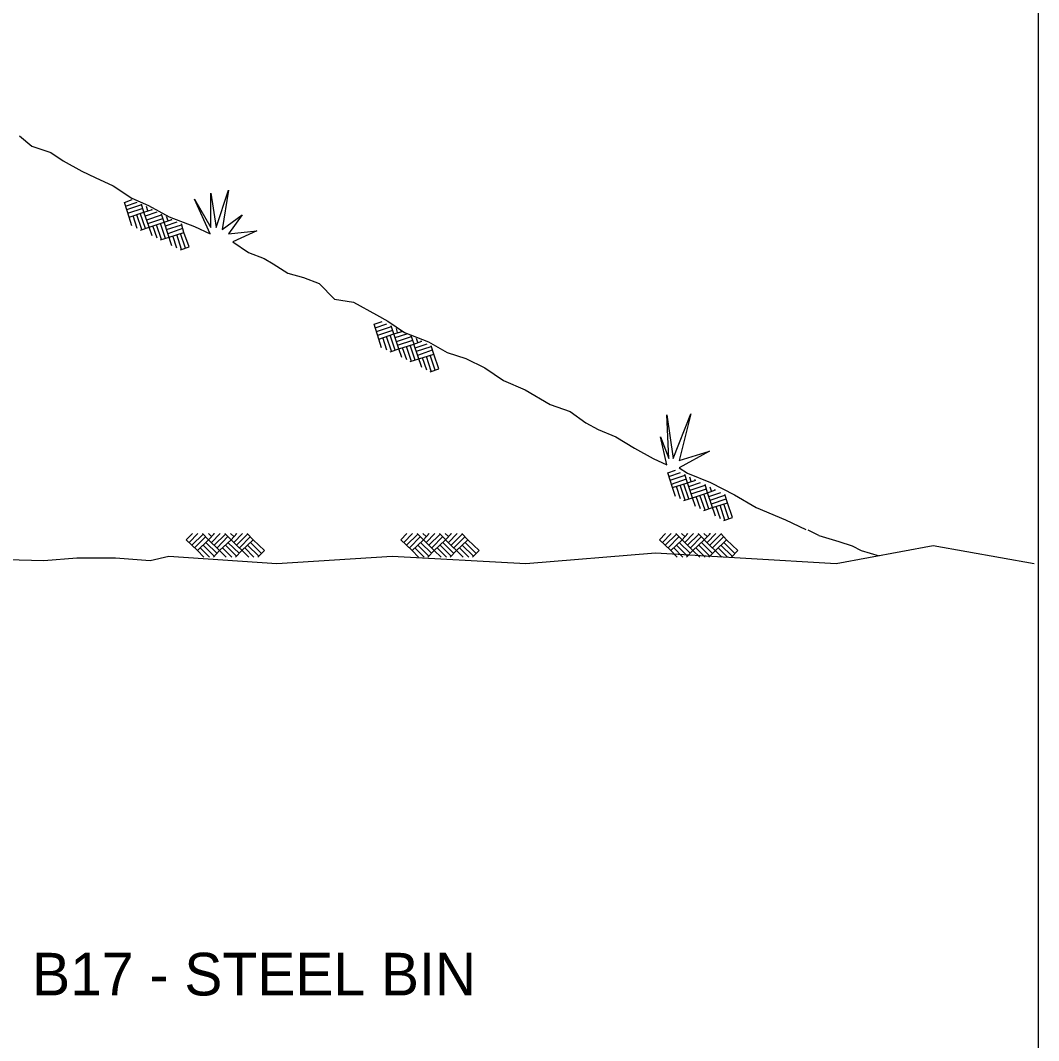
# Model space of a CAD drawing. Extents: x -0.04 to 2.79, y -0.02 to 1.81.
# Drawn here: x 2.2693 to 2.5178, y 0.5127 to 0.7618 of the extents above; entities that cross this region are included whole.
import ezdxf

# ---------------------------------------------------------------- set-up
doc = ezdxf.new("R2010")
doc.units = 0
doc.layers.add('G-ANNO-TTLB', color=7, linetype='Continuous')
doc.layers.add('Level 1', color=7, linetype='Continuous')

msp = doc.modelspace()

# ---------------------------------------------------------------- linework, layer by layer
at = {"layer": 'G-ANNO-TTLB'}
msp.add_line((2.51784, 0.08028), (2.51784, 1.71305), dxfattribs=at)
at = {"layer": 'Level 1'}
for p, q in [((2.29464, 0.71733), (2.29655, 0.71801)), ((2.2958, 0.71371), (2.29464, 0.71733)), ((2.29491, 0.71644), (2.29778, 0.7174)), ((2.29526, 0.71555), (2.29888, 0.71678)), ((2.29553, 0.71466), (2.29922, 0.71589)), ((2.2958, 0.71371), (2.29943, 0.71494)), ((2.29943, 0.71494), (2.29881, 0.71692)), ((2.29943, 0.71494), (2.30148, 0.71555)), ((2.29943, 0.71494), (2.30148, 0.71555)), ((2.30066, 0.71131), (2.29943, 0.71494)), ((2.29977, 0.71405), (2.30264, 0.715)), ((2.30038, 0.71528), (2.30004, 0.7163)), ((2.30134, 0.71555), (2.30127, 0.71569)), ((2.29649, 0.71159), (2.2958, 0.71371)), ((2.29778, 0.71097), (2.29676, 0.71405)), ((2.29888, 0.7107), (2.29765, 0.71432)), ((2.29977, 0.71097), (2.29854, 0.71466)), ((2.30011, 0.71309), (2.30373, 0.71432)), ((2.30038, 0.7122), (2.30407, 0.71343)), ((2.30066, 0.71131), (2.30435, 0.71248)), ((2.30435, 0.71248), (2.30373, 0.71446)), ((2.30435, 0.71248), (2.30633, 0.71316)), ((2.30435, 0.71248), (2.30633, 0.71316)), ((2.30626, 0.70673), (2.30435, 0.71248)), ((2.30469, 0.71159), (2.30756, 0.71254)), ((2.3053, 0.71282), (2.30496, 0.71384)), ((2.30619, 0.71309), (2.30612, 0.71323)), ((2.29861, 0.71056), (2.30066, 0.71131)), ((2.30141, 0.70919), (2.30066, 0.71131)), ((2.30264, 0.70858), (2.30161, 0.71159)), ((2.30373, 0.70824), (2.3025, 0.71186)), ((2.30469, 0.70851), (2.30346, 0.7122)), ((2.30496, 0.7107), (2.30858, 0.71186)), ((2.3053, 0.70974), (2.30893, 0.71104)), ((2.30558, 0.70885), (2.3092, 0.71001)), ((2.3092, 0.71001), (2.30858, 0.71207)), ((2.31043, 0.70646), (2.3092, 0.71001)), ((2.30346, 0.70817), (2.30558, 0.70885)), ((2.30749, 0.70612), (2.30647, 0.70913)), ((2.30858, 0.70585), (2.30742, 0.70947)), ((2.30954, 0.70612), (2.30831, 0.70974)), ((2.30831, 0.70571), (2.31043, 0.70646)), ((2.35561, 0.6876), (2.35759, 0.68828)), ((2.35677, 0.68397), (2.35561, 0.6876)), ((2.35588, 0.68671), (2.35875, 0.68766)), ((2.35622, 0.68582), (2.35985, 0.68705)), ((2.3565, 0.68493), (2.36019, 0.68616)), ((2.35677, 0.68397), (2.36046, 0.6852)), ((2.36074, 0.68124), (2.35951, 0.68493)), ((2.36046, 0.6852), (2.35978, 0.68719)), ((2.36046, 0.6852), (2.36244, 0.68582)), ((2.36046, 0.6852), (2.36244, 0.68582)), ((2.36169, 0.68158), (2.36046, 0.6852)), ((2.36074, 0.68431), (2.36361, 0.68527)), ((2.36135, 0.68555), (2.36108, 0.68657)), ((2.36231, 0.68582), (2.36224, 0.68596)), ((2.35746, 0.68185), (2.35677, 0.68397)), ((2.35875, 0.68124), (2.35773, 0.68431)), ((2.35985, 0.68097), (2.35862, 0.68459)), ((2.36108, 0.68336), (2.36477, 0.68459)), ((2.36135, 0.68247), (2.36504, 0.6837)), ((2.36169, 0.68158), (2.36532, 0.68274)), ((2.36566, 0.67878), (2.36443, 0.68247)), ((2.36538, 0.68274), (2.3647, 0.68472)), ((2.36532, 0.68274), (2.3673, 0.68343)), ((2.36532, 0.68274), (2.3673, 0.68343)), ((2.36723, 0.677), (2.36532, 0.68274)), ((2.36566, 0.68185), (2.36853, 0.68281)), ((2.36627, 0.68308), (2.36593, 0.68411)), ((2.36716, 0.68336), (2.36709, 0.68349)), ((2.35957, 0.68083), (2.36169, 0.68158)), ((2.36238, 0.67946), (2.36169, 0.68158)), ((2.36361, 0.67885), (2.36258, 0.68185)), ((2.36477, 0.6785), (2.36354, 0.68213)), ((2.36593, 0.68097), (2.36955, 0.68213)), ((2.36627, 0.68001), (2.3699, 0.68131)), ((2.36655, 0.67912), (2.37017, 0.68028)), ((2.37051, 0.67639), (2.36928, 0.68001)), ((2.37017, 0.68028), (2.36955, 0.68233)), ((2.3714, 0.67673), (2.37017, 0.68028)), ((2.36443, 0.67844), (2.36655, 0.67912)), ((2.36846, 0.67639), (2.36743, 0.67939)), ((2.36955, 0.67611), (2.36839, 0.67974)), ((2.36928, 0.67598), (2.3714, 0.67673)), ((2.42731, 0.6513), (2.42922, 0.65198)), ((2.42847, 0.64768), (2.42731, 0.6513)), ((2.42758, 0.65041), (2.43045, 0.65137)), ((2.42792, 0.64952), (2.43155, 0.65069)), ((2.43209, 0.64884), (2.43148, 0.65089)), ((2.43305, 0.64918), (2.43271, 0.65028)), ((2.4282, 0.64857), (2.43189, 0.6498)), ((2.42847, 0.64768), (2.43209, 0.64884)), ((2.42916, 0.64556), (2.42847, 0.64768)), ((2.43045, 0.64494), (2.42943, 0.64795)), ((2.43155, 0.6446), (2.43032, 0.64829)), ((2.43244, 0.64494), (2.43121, 0.64857)), ((2.43209, 0.64884), (2.43414, 0.64952)), ((2.43209, 0.64884), (2.43414, 0.64952)), ((2.43332, 0.64522), (2.43209, 0.64884)), ((2.43244, 0.64795), (2.43531, 0.64891)), ((2.43278, 0.64706), (2.4364, 0.64829)), ((2.43401, 0.64952), (2.43394, 0.64966)), ((2.43702, 0.64645), (2.4364, 0.64843)), ((2.43797, 0.64679), (2.43763, 0.64782)), ((2.43127, 0.64453), (2.43332, 0.64522)), ((2.43305, 0.64618), (2.43674, 0.64741)), ((2.43332, 0.64522), (2.43702, 0.64645)), ((2.43408, 0.6431), (2.43332, 0.64522)), ((2.43531, 0.64248), (2.43428, 0.64556)), ((2.4364, 0.64221), (2.43517, 0.64583)), ((2.43736, 0.64248), (2.43613, 0.64618)), ((2.43702, 0.64645), (2.439, 0.64713)), ((2.43702, 0.64645), (2.439, 0.64713)), ((2.43893, 0.64071), (2.43702, 0.64645)), ((2.43736, 0.64556), (2.44023, 0.64652)), ((2.43763, 0.6446), (2.44125, 0.64583)), ((2.43886, 0.64706), (2.43879, 0.6472)), ((2.44187, 0.64399), (2.44125, 0.64597)), ((2.43613, 0.64207), (2.43825, 0.64283)), ((2.43797, 0.64371), (2.4416, 0.64494)), ((2.43825, 0.64283), (2.44187, 0.64399)), ((2.44016, 0.64009), (2.43913, 0.6431)), ((2.44125, 0.63975), (2.44009, 0.64344)), ((2.44221, 0.64009), (2.44098, 0.64371)), ((2.4431, 0.64037), (2.44187, 0.64399)), ((2.44098, 0.63968), (2.4431, 0.64037)), ((2.30975, 0.63497), (2.31125, 0.63647)), ((2.31043, 0.63428), (2.31255, 0.63647)), ((2.31111, 0.63367), (2.31385, 0.63633)), ((2.3118, 0.63298), (2.31453, 0.63572)), ((2.31521, 0.63497), (2.31371, 0.63647)), ((2.3159, 0.63572), (2.31515, 0.63647)), ((2.31521, 0.63497), (2.31665, 0.63647)), ((2.31521, 0.63497), (2.31665, 0.63647)), ((2.3159, 0.63428), (2.31802, 0.63647)), ((2.31658, 0.63633), (2.31644, 0.63647)), ((2.31658, 0.63367), (2.31932, 0.63633)), ((2.31726, 0.63298), (2.31993, 0.63572)), ((2.32068, 0.63497), (2.31918, 0.63647)), ((2.32137, 0.63572), (2.32055, 0.63647)), ((2.32068, 0.63497), (2.32212, 0.63647)), ((2.32068, 0.63497), (2.32212, 0.63647)), ((2.32137, 0.63428), (2.32348, 0.63647)), ((2.32198, 0.63633), (2.32191, 0.63647)), ((2.32198, 0.63367), (2.32472, 0.63633)), ((2.32273, 0.63298), (2.3254, 0.63572)), ((2.32608, 0.63497), (2.32465, 0.63647)), ((2.36217, 0.63497), (2.36361, 0.63647)), ((2.36285, 0.63428), (2.36497, 0.63647)), ((2.36354, 0.63367), (2.36627, 0.63633)), ((2.36422, 0.63298), (2.36696, 0.63572)), ((2.36764, 0.63497), (2.36614, 0.63647)), ((2.36832, 0.63572), (2.3675, 0.63647)), ((2.36764, 0.63497), (2.36907, 0.63647)), ((2.36764, 0.63497), (2.36907, 0.63647)), ((2.36832, 0.63428), (2.37044, 0.63647)), ((2.36901, 0.63633), (2.36887, 0.63647)), ((2.36901, 0.63367), (2.37174, 0.63633)), ((2.36969, 0.63298), (2.37236, 0.63572)), ((2.37311, 0.63497), (2.3716, 0.63647)), ((2.37379, 0.63572), (2.37297, 0.63647)), ((2.37304, 0.63497), (2.37454, 0.63647)), ((2.37304, 0.63497), (2.37454, 0.63647)), ((2.37379, 0.63428), (2.37591, 0.63647)), ((2.37441, 0.63633), (2.37434, 0.63647)), ((2.37441, 0.63367), (2.37714, 0.63633)), ((2.37509, 0.63298), (2.37782, 0.63572)), ((2.37851, 0.63497), (2.37707, 0.63647)), ((2.42533, 0.63497), (2.42676, 0.63647)), ((2.42601, 0.63428), (2.42813, 0.63647)), ((2.42669, 0.63367), (2.42943, 0.63633)), ((2.42738, 0.63298), (2.43011, 0.63572)), ((2.4308, 0.63497), (2.42929, 0.63647)), ((2.43148, 0.63572), (2.43066, 0.63647)), ((2.4308, 0.63497), (2.43223, 0.63647)), ((2.4308, 0.63497), (2.43223, 0.63647)), ((2.43148, 0.63428), (2.4336, 0.63647)), ((2.43216, 0.63633), (2.43203, 0.63647)), ((2.43216, 0.63367), (2.4349, 0.63633)), ((2.43285, 0.63298), (2.43551, 0.63572)), ((2.43626, 0.63497), (2.43476, 0.63647)), ((2.43695, 0.63572), (2.43613, 0.63647)), ((2.4362, 0.63497), (2.4377, 0.63647)), ((2.4362, 0.63497), (2.4377, 0.63647)), ((2.43695, 0.63428), (2.43907, 0.63647)), ((2.43756, 0.63633), (2.43749, 0.63647)), ((2.43756, 0.63367), (2.4403, 0.63633)), ((2.43825, 0.63298), (2.44098, 0.63572)), ((2.44166, 0.63497), (2.44023, 0.63647)), ((2.31248, 0.6323), (2.30975, 0.63497)), ((2.31248, 0.6323), (2.31521, 0.63497)), ((2.31542, 0.63073), (2.31316, 0.63298)), ((2.31658, 0.63093), (2.31385, 0.63367)), ((2.31726, 0.63162), (2.31453, 0.63428)), ((2.31788, 0.6323), (2.31521, 0.63497)), ((2.31788, 0.6323), (2.32068, 0.63497)), ((2.32089, 0.63073), (2.31863, 0.63298)), ((2.32198, 0.63093), (2.31932, 0.63367)), ((2.32273, 0.63162), (2.31993, 0.63428)), ((2.32499, 0.63073), (2.32068, 0.63497)), ((2.32335, 0.6323), (2.32608, 0.63497)), ((2.32629, 0.63073), (2.32403, 0.63298)), ((2.32745, 0.63093), (2.32472, 0.63367)), ((2.32813, 0.63162), (2.3254, 0.63428)), ((2.32882, 0.6323), (2.32608, 0.63497)), ((2.36491, 0.6323), (2.36217, 0.63497)), ((2.36491, 0.6323), (2.36764, 0.63497)), ((2.36784, 0.63073), (2.36559, 0.63298)), ((2.36901, 0.63093), (2.36627, 0.63367)), ((2.36969, 0.63162), (2.36696, 0.63428)), ((2.37031, 0.6323), (2.36764, 0.63497)), ((2.37031, 0.6323), (2.37304, 0.63497)), ((2.37331, 0.63073), (2.37099, 0.63298)), ((2.37441, 0.63093), (2.37174, 0.63367)), ((2.37509, 0.63162), (2.37236, 0.63428)), ((2.37735, 0.63073), (2.37304, 0.63497)), ((2.37577, 0.6323), (2.37851, 0.63497)), ((2.37871, 0.63073), (2.37646, 0.63298)), ((2.37987, 0.63093), (2.37714, 0.63367)), ((2.38056, 0.63162), (2.37782, 0.63428)), ((2.38124, 0.6323), (2.37851, 0.63497)), ((2.42806, 0.6323), (2.42533, 0.63497)), ((2.42806, 0.6323), (2.4308, 0.63497)), ((2.431, 0.63073), (2.42875, 0.63298)), ((2.43216, 0.63093), (2.42943, 0.63367)), ((2.43285, 0.63162), (2.43011, 0.63428)), ((2.43346, 0.6323), (2.4308, 0.63497)), ((2.43346, 0.6323), (2.4362, 0.63497)), ((2.43647, 0.63073), (2.43414, 0.63298)), ((2.43756, 0.63093), (2.4349, 0.63367)), ((2.43825, 0.63162), (2.43551, 0.63428)), ((2.4405, 0.63073), (2.4362, 0.63497)), ((2.43893, 0.6323), (2.44166, 0.63497)), ((2.44187, 0.63073), (2.43961, 0.63298)), ((2.44303, 0.63093), (2.4403, 0.63367)), ((2.44371, 0.63162), (2.44098, 0.63428)), ((2.4444, 0.6323), (2.44166, 0.63497)), ((2.31405, 0.63073), (2.31248, 0.6323)), ((2.31638, 0.63073), (2.31788, 0.6323)), ((2.31952, 0.63073), (2.31788, 0.6323)), ((2.32178, 0.63073), (2.32335, 0.6323)), ((2.32724, 0.63073), (2.32882, 0.6323)), ((2.36648, 0.63073), (2.36491, 0.6323)), ((2.36873, 0.63073), (2.37031, 0.6323)), ((2.37195, 0.63073), (2.37031, 0.6323)), ((2.3742, 0.63073), (2.37577, 0.6323)), ((2.37967, 0.63073), (2.38124, 0.6323)), ((2.42963, 0.63073), (2.42806, 0.6323)), ((2.43189, 0.63073), (2.43346, 0.6323)), ((2.4351, 0.63073), (2.43346, 0.6323)), ((2.43736, 0.63073), (2.43893, 0.6323)), ((2.44283, 0.63073), (2.4444, 0.6323))]:
    msp.add_line(p, q, dxfattribs=at)
for points in [[(2.26901, 0.7336), (2.27209, 0.73107), (2.27666, 0.72949), (2.27967, 0.72744), (2.28425, 0.72492), (2.28753, 0.72341), (2.29191, 0.72136), (2.29649, 0.71835), (2.30052, 0.71658), (2.30558, 0.71377), (2.31173, 0.71145), (2.31556, 0.70967), (2.31173, 0.71808), (2.31576, 0.71118), (2.31576, 0.71958), (2.31706, 0.71118), (2.32007, 0.72034), (2.31856, 0.7107), (2.32342, 0.71425), (2.32007, 0.70967), (2.32697, 0.71042), (2.32109, 0.70769), (2.32492, 0.70509), (2.32875, 0.70359), (2.331, 0.70229), (2.33456, 0.70004), (2.33839, 0.69901), (2.34221, 0.69751), (2.34597, 0.69368), (2.35062, 0.69293), (2.35616, 0.68985), (2.35896, 0.68835), (2.36306, 0.68555), (2.36887, 0.68329), (2.37345, 0.68069), (2.37803, 0.67919), (2.38261, 0.67693), (2.38719, 0.67386), (2.39252, 0.6716), (2.3986, 0.66798), (2.40346, 0.66627), (2.40728, 0.66347), (2.41029, 0.6619), (2.4146, 0.66012), (2.41918, 0.65732), (2.42376, 0.65479), (2.4271, 0.65328), (2.42553, 0.66012), (2.42758, 0.65479), (2.4271, 0.66545), (2.42861, 0.65479), (2.43291, 0.66572), (2.43011, 0.65431), (2.43749, 0.65656), (2.43011, 0.65253), (2.43216, 0.65123), (2.43777, 0.64891), (2.44358, 0.6459), (2.44891, 0.64283), (2.45602, 0.63982), (2.46101, 0.63749)], [(2.46415, 0.63599), (2.46155, 0.63729)], [(2.46415, 0.63599), (2.46907, 0.63456), (2.47235, 0.63346), (2.47454, 0.63237), (2.47891, 0.63107)], [(2.26593, 0.63011), (2.27496, 0.62991), (2.28302, 0.63052), (2.29245, 0.63052), (2.30093, 0.62991), (2.30551, 0.63093), (2.33189, 0.62916), (2.36005, 0.63093), (2.39266, 0.62916), (2.4243, 0.63175), (2.46839, 0.62916), (2.49211, 0.63353), (2.51678, 0.62916)]]:
    msp.add_lwpolyline(points, dxfattribs=at)

# ---------------------------------------------------------------- texts
msp.add_text('B17 - STEEL BIN', height=0.0104167).set_placement((2.27212, 0.52371))

doc.saveas('drawing.dxf')
